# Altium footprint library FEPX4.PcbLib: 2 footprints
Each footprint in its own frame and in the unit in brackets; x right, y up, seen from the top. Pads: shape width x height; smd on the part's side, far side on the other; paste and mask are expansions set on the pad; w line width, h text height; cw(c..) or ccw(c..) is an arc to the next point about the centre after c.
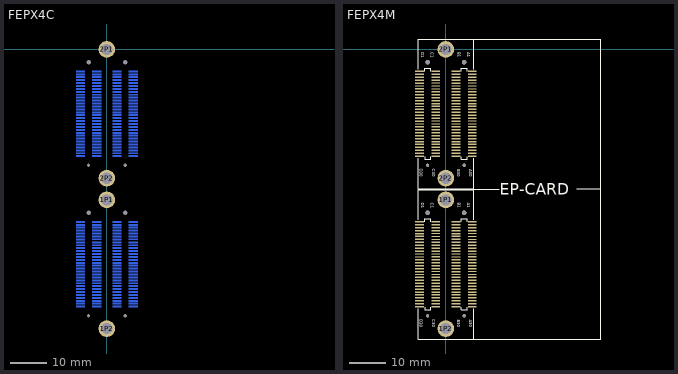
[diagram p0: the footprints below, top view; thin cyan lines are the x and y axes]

## FEPX4C [mm]
pads (252):
  round 0 hole 0.889: 0(-5,-72.869) 0(-5,-31.7) 0(5,-72.869) 0(5,-31.7)
  round 0 hole 1.2: 0(-5,-44.669) 0(-5,-3.5) 0(5,-44.669) 0(5,-3.5)
  rect 2.4x0.4 smd far side: 1A1(7.2,-47.169) 1A2(7.2,-47.969) 1A3(7.2,-48.769) 1A4(7.2,-49.569) 1A8(7.2,-52.769) 1A9(7.2,-53.569) 1A10(7.2,-54.369) 1A11(7.2,-55.169) 1A12(7.2,-55.969) 1A13(7.2,-56.769) 1A14(7.2,-57.569) 1A15(7.2,-58.369) 1A16(7.2,-59.169) 1A17(7.2,-59.969) 1A20(7.2,-62.369) 1A21(7.2,-63.169) 1A22(7.2,-63.969) 1A23(7.2,-64.769) 1A24(7.2,-65.569) 1A25(7.2,-66.369) 1A26(7.2,-67.169) 1A27(7.2,-67.969) 1A28(7.2,-68.769) 1A29(7.2,-69.569) 1A30(7.2,-70.369) 1B1(2.8,-47.169) 1B2(2.8,-47.969) 1B3(2.8,-48.769) 1B4(2.8,-49.569) 1B5(2.8,-50.369) 1B6(2.8,-51.169) 1B7(2.8,-51.969) 1B8(2.8,-52.769) 1B9(2.8,-53.569) 1B10(2.8,-54.369) 1B11(2.8,-55.169) 1B12(2.8,-55.969) 1B14(2.8,-57.569) 1B15(2.8,-58.369) 1B16(2.8,-59.169) 1B17(2.8,-59.969) 1B18(2.8,-60.769) 1B19(2.8,-61.569) 1B20(2.8,-62.369) 1B21(2.8,-63.169) 1B22(2.8,-63.969) 1B23(2.8,-64.769) 1B24(2.8,-65.569) 1B25(2.8,-66.369) 1B26(2.8,-67.169) 1B27(2.8,-67.969) 1B28(2.8,-68.769) 1B29(2.8,-69.569) 1B30(2.8,-70.369) 1C1(-2.8,-47.169) 1C2(-2.8,-47.969) 1C3(-2.8,-48.769) 1C4(-2.8,-49.569) 1C8(-2.8,-52.769) 1C9(-2.8,-53.569) 1C10(-2.8,-54.369) 1C11(-2.8,-55.169) 1C12(-2.8,-55.969) 1C13(-2.8,-56.769) 1C14(-2.8,-57.569) 1C15(-2.8,-58.369) 1C16(-2.8,-59.169) 1C17(-2.8,-59.969) 1C20(-2.8,-62.369) 1C21(-2.8,-63.169) 1C22(-2.8,-63.969) 1C23(-2.8,-64.769) 1C24(-2.8,-65.569) 1C25(-2.8,-66.369) 1C26(-2.8,-67.169) 1C27(-2.8,-67.969) 1C28(-2.8,-68.769) 1C29(-2.8,-69.569) 1C30(-2.8,-70.369) 1D1(-7.2,-47.169) 1D2(-7.2,-47.969) 1D3(-7.2,-48.769) 1D4(-7.2,-49.569) 1D5(-7.2,-50.369) 1D6(-7.2,-51.169) 1D7(-7.2,-51.969) 1D8(-7.2,-52.769) 1D9(-7.2,-53.569) 1D10(-7.2,-54.369) 1D11(-7.2,-55.169) 1D12(-7.2,-55.969) 1D14(-7.2,-57.569) 1D15(-7.2,-58.369) 1D16(-7.2,-59.169) 1D17(-7.2,-59.969) 1D18(-7.2,-60.769) 1D19(-7.2,-61.569) 1D20(-7.2,-62.369) 1D21(-7.2,-63.169) 1D22(-7.2,-63.969) 1D23(-7.2,-64.769) 1D24(-7.2,-65.569) 1D25(-7.2,-66.369) 1D26(-7.2,-67.169) 1D27(-7.2,-67.969) 1D28(-7.2,-68.769) 1D29(-7.2,-69.569) 1D30(-7.2,-70.369) 2A1(7.2,-6) 2A2(7.2,-6.8) 2A3(7.2,-7.6) 2A4(7.2,-8.4) 2A8(7.2,-11.6) 2A9(7.2,-12.4) 2A10(7.2,-13.2) 2A11(7.2,-14) 2A12(7.2,-14.8) 2A13(7.2,-15.6) 2A14(7.2,-16.4) 2A15(7.2,-17.2) 2A16(7.2,-18) 2A17(7.2,-18.8) 2A20(7.2,-21.2) 2A21(7.2,-22) 2A22(7.2,-22.8) 2A23(7.2,-23.6) 2A24(7.2,-24.4) 2A25(7.2,-25.2) 2A26(7.2,-26) 2A27(7.2,-26.8) 2A28(7.2,-27.6) 2A29(7.2,-28.4) 2A30(7.2,-29.2) 2B1(2.8,-6) 2B2(2.8,-6.8) 2B3(2.8,-7.6) 2B4(2.8,-8.4) 2B5(2.8,-9.2) 2B6(2.8,-10) 2B7(2.8,-10.8) 2B8(2.8,-11.6) 2B9(2.8,-12.4) 2B10(2.8,-13.2) 2B11(2.8,-14) 2B12(2.8,-14.8) 2B14(2.8,-16.4) 2B15(2.8,-17.2) 2B16(2.8,-18) 2B17(2.8,-18.8) 2B18(2.8,-19.6) 2B19(2.8,-20.4) 2B20(2.8,-21.2) 2B21(2.8,-22) 2B22(2.8,-22.8) 2B23(2.8,-23.6) 2B24(2.8,-24.4) 2B25(2.8,-25.2) 2B26(2.8,-26) 2B27(2.8,-26.8) 2B28(2.8,-27.6) 2B29(2.8,-28.4) 2B30(2.8,-29.2) 2C1(-2.8,-6) 2C2(-2.8,-6.8) 2C3(-2.8,-7.6) 2C4(-2.8,-8.4) 2C8(-2.8,-11.6) 2C9(-2.8,-12.4) 2C10(-2.8,-13.2) 2C11(-2.8,-14) 2C12(-2.8,-14.8) 2C13(-2.8,-15.6) 2C14(-2.8,-16.4) 2C15(-2.8,-17.2) 2C16(-2.8,-18) 2C17(-2.8,-18.8) 2C20(-2.8,-21.2) 2C21(-2.8,-22) 2C22(-2.8,-22.8) 2C23(-2.8,-23.6) 2C24(-2.8,-24.4) 2C25(-2.8,-25.2) 2C26(-2.8,-26) 2C27(-2.8,-26.8) 2C28(-2.8,-27.6) 2C29(-2.8,-28.4) 2C30(-2.8,-29.2) 2D1(-7.2,-6) 2D2(-7.2,-6.8) 2D3(-7.2,-7.6) 2D4(-7.2,-8.4) 2D5(-7.2,-9.2) 2D6(-7.2,-10) 2D7(-7.2,-10.8) 2D8(-7.2,-11.6) 2D9(-7.2,-12.4) 2D10(-7.2,-13.2) 2D11(-7.2,-14) 2D12(-7.2,-14.8) 2D14(-7.2,-16.4) 2D15(-7.2,-17.2) 2D16(-7.2,-18) 2D17(-7.2,-18.8) 2D18(-7.2,-19.6) 2D19(-7.2,-20.4) 2D20(-7.2,-21.2) 2D21(-7.2,-22) 2D22(-7.2,-22.8) 2D23(-7.2,-23.6) 2D24(-7.2,-24.4) 2D25(-7.2,-25.2) 2D26(-7.2,-26) 2D27(-7.2,-26.8) 2D28(-7.2,-27.6) 2D29(-7.2,-28.4) 2D30(-7.2,-29.2)
  rect 2.4x0.33 smd far side: 1A5(7.2,-50.369) 1A6(7.2,-51.169) 1A7(7.2,-51.969) 1A18(7.2,-60.769) 1A19(7.2,-61.569) 1B13(2.8,-56.769) 1C5(-2.8,-50.369) 1C6(-2.8,-51.169) 1C7(-2.8,-51.969) 1C18(-2.8,-60.769) 1C19(-2.8,-61.569) 1D13(-7.2,-56.769) 2A5(7.2,-9.2) 2A6(7.2,-10) 2A7(7.2,-10.8) 2A18(7.2,-19.6) 2A19(7.2,-20.4) 2B13(2.8,-15.6) 2C5(-2.8,-9.2) 2C6(-2.8,-10) 2C7(-2.8,-10.8) 2C18(-2.8,-19.6) 2C19(-2.8,-20.4) 2D13(-7.2,-15.6)
  round 4.57 hole 3.1: 1P1(0,-41.169) 1P2(0,-76.369) 2P1(0,0) 2P2(0,-35.2)
Bottom Overlay:
  lines w0.152: -7.62,-79.219 42.383,-79.219 ; -7.611,2.855 42.392,2.855 42.392,-79.193 ; -7.595,-38.192 7.62,-38.192 ; -5.8,-70.469 -5.8,-71.269 -4.2,-71.269 ; -5.8,-47.169 -5.8,-46.369 -4.2,-46.369 -4.2,-47.169 ; -5.8,-29.3 -5.8,-30.1 -4.2,-30.1 -4.2,-29.3 ; -5.8,-6 -5.8,-5.2 -4.2,-5.2 -4.2,-6 ; 4.2,-70.469 4.2,-71.269 5.8,-71.269 5.8,-70.469 ; 4.2,-47.169 4.2,-46.369 5.8,-46.369 5.8,-47.169 ; 4.2,-29.3 4.2,-30.1 5.8,-30.1 5.8,-29.3 ; 4.2,-6 4.2,-5.2 5.8,-5.2 5.8,-6 ; -4.2,-71.269 -4.2,-70.469 -4.2,-71.269
  lines w0.203: -7.62,-70.964 -7.62,-79.219 7.62,-79.219 7.62,-70.964 ; -7.62,-46.574 -7.62,-38.1 ; -7.62,-38.227 -7.62,-29.795 ; -7.62,-5.405 -7.62,2.85 7.62,2.85 7.62,-5.405 ; 7.62,-46.574 7.62,-38.227 7.62,-29.795
  text "D1" at -6.731,-0.762 h0.76
  text "C1" at -4.191,-0.762 h0.76
  text "B1" at 3.302,-0.762 h0.76
  text "A1" at 5.842,-0.762 h0.76
  text "D30" at -7.112,-32.639 h0.76
  text "C30" at -3.683,-32.639 h0.76
  text "B30" at 3.175,-32.766 h0.76
  text "A30" at 6.35,-32.766 h0.76
  text "D1" at -6.731,-41.931 h0.76
  text "C1" at -4.191,-41.931 h0.76
  text "B1" at 3.302,-41.931 h0.76
  text "A1" at 5.842,-41.931 h0.76
  text "D30" at -7.112,-73.808 h0.76
  text "C30" at -3.683,-73.808 h0.76
  text "B30" at 3.175,-73.935 h0.76
  text "A30" at 6.35,-73.935 h0.76

## FEPX4M [mm]
pads (252):
  round 0.889 hole 0.889: 0(-5,-72.869) 0(-5,-31.7) 0(5,-72.869) 0(5,-31.7)
  round 1.2 hole 1.2: 0(-5,-44.669) 0(-5,-3.5) 0(5,-44.669) 0(5,-3.5)
  rect 2.4x0.4 smd: 1A1(7.2,-47.169) 1A2(7.2,-47.969) 1A3(7.2,-48.769) 1A4(7.2,-49.569) 1A8(7.2,-52.769) 1A9(7.2,-53.569) 1A10(7.2,-54.369) 1A11(7.2,-55.169) 1A12(7.2,-55.969) 1A13(7.2,-56.769) 1A14(7.2,-57.569) 1A15(7.2,-58.369) 1A16(7.2,-59.169) 1A17(7.2,-59.969) 1A20(7.2,-62.369) 1A21(7.2,-63.169) 1A22(7.2,-63.969) 1A23(7.2,-64.769) 1A24(7.2,-65.569) 1A25(7.2,-66.369) 1A26(7.2,-67.169) 1A27(7.2,-67.969) 1A28(7.2,-68.769) 1A29(7.2,-69.569) 1A30(7.2,-70.369) 1B1(2.8,-47.169) 1B2(2.8,-47.969) 1B3(2.8,-48.769) 1B4(2.8,-49.569) 1B5(2.8,-50.369) 1B6(2.8,-51.169) 1B7(2.8,-51.969) 1B8(2.8,-52.769) 1B9(2.8,-53.569) 1B10(2.8,-54.369) 1B11(2.8,-55.169) 1B12(2.8,-55.969) 1B14(2.8,-57.569) 1B15(2.8,-58.369) 1B16(2.8,-59.169) 1B17(2.8,-59.969) 1B18(2.8,-60.769) 1B19(2.8,-61.569) 1B20(2.8,-62.369) 1B21(2.8,-63.169) 1B22(2.8,-63.969) 1B23(2.8,-64.769) 1B24(2.8,-65.569) 1B25(2.8,-66.369) 1B26(2.8,-67.169) 1B27(2.8,-67.969) 1B28(2.8,-68.769) 1B29(2.8,-69.569) 1B30(2.8,-70.369) 1C1(-2.8,-47.169) 1C2(-2.8,-47.969) 1C3(-2.8,-48.769) 1C4(-2.8,-49.569) 1C8(-2.8,-52.769) 1C9(-2.8,-53.569) 1C10(-2.8,-54.369) 1C11(-2.8,-55.169) 1C12(-2.8,-55.969) 1C13(-2.8,-56.769) 1C14(-2.8,-57.569) 1C15(-2.8,-58.369) 1C16(-2.8,-59.169) 1C17(-2.8,-59.969) 1C20(-2.8,-62.369) 1C21(-2.8,-63.169) 1C22(-2.8,-63.969) 1C23(-2.8,-64.769) 1C24(-2.8,-65.569) 1C25(-2.8,-66.369) 1C26(-2.8,-67.169) 1C27(-2.8,-67.969) 1C28(-2.8,-68.769) 1C29(-2.8,-69.569) 1C30(-2.8,-70.369) 1D1(-7.2,-47.169) 1D2(-7.2,-47.969) 1D3(-7.2,-48.769) 1D4(-7.2,-49.569) 1D5(-7.2,-50.369) 1D6(-7.2,-51.169) 1D7(-7.2,-51.969) 1D8(-7.2,-52.769) 1D9(-7.2,-53.569) 1D10(-7.2,-54.369) 1D11(-7.2,-55.169) 1D12(-7.2,-55.969) 1D14(-7.2,-57.569) 1D15(-7.2,-58.369) 1D16(-7.2,-59.169) 1D17(-7.2,-59.969) 1D18(-7.2,-60.769) 1D19(-7.2,-61.569) 1D20(-7.2,-62.369) 1D21(-7.2,-63.169) 1D22(-7.2,-63.969) 1D23(-7.2,-64.769) 1D24(-7.2,-65.569) 1D25(-7.2,-66.369) 1D26(-7.2,-67.169) 1D27(-7.2,-67.969) 1D28(-7.2,-68.769) 1D29(-7.2,-69.569) 1D30(-7.2,-70.369) 2A1(7.2,-6) 2A2(7.2,-6.8) 2A3(7.2,-7.6) 2A4(7.2,-8.4) 2A8(7.2,-11.6) 2A9(7.2,-12.4) 2A10(7.2,-13.2) 2A11(7.2,-14) 2A12(7.2,-14.8) 2A13(7.2,-15.6) 2A14(7.2,-16.4) 2A15(7.2,-17.2) 2A16(7.2,-18) 2A17(7.2,-18.8) 2A20(7.2,-21.2) 2A21(7.2,-22) 2A22(7.2,-22.8) 2A23(7.2,-23.6) 2A24(7.2,-24.4) 2A25(7.2,-25.2) 2A26(7.2,-26) 2A27(7.2,-26.8) 2A28(7.2,-27.6) 2A29(7.2,-28.4) 2A30(7.2,-29.2) 2B1(2.8,-6) 2B2(2.8,-6.8) 2B3(2.8,-7.6) 2B4(2.8,-8.4) 2B5(2.8,-9.2) 2B6(2.8,-10) 2B7(2.8,-10.8) 2B8(2.8,-11.6) 2B9(2.8,-12.4) 2B10(2.8,-13.2) 2B11(2.8,-14) 2B12(2.8,-14.8) 2B14(2.8,-16.4) 2B15(2.8,-17.2) 2B16(2.8,-18) 2B17(2.8,-18.8) 2B18(2.8,-19.6) 2B19(2.8,-20.4) 2B20(2.8,-21.2) 2B21(2.8,-22) 2B22(2.8,-22.8) 2B23(2.8,-23.6) 2B24(2.8,-24.4) 2B25(2.8,-25.2) 2B26(2.8,-26) 2B27(2.8,-26.8) 2B28(2.8,-27.6) 2B29(2.8,-28.4) 2B30(2.8,-29.2) 2C1(-2.8,-6) 2C2(-2.8,-6.8) 2C3(-2.8,-7.6) 2C4(-2.8,-8.4) 2C8(-2.8,-11.6) 2C9(-2.8,-12.4) 2C10(-2.8,-13.2) 2C11(-2.8,-14) 2C12(-2.8,-14.8) 2C13(-2.8,-15.6) 2C14(-2.8,-16.4) 2C15(-2.8,-17.2) 2C16(-2.8,-18) 2C17(-2.8,-18.8) 2C20(-2.8,-21.2) 2C21(-2.8,-22) 2C22(-2.8,-22.8) 2C23(-2.8,-23.6) 2C24(-2.8,-24.4) 2C25(-2.8,-25.2) 2C26(-2.8,-26) 2C27(-2.8,-26.8) 2C28(-2.8,-27.6) 2C29(-2.8,-28.4) 2C30(-2.8,-29.2) 2D1(-7.2,-6) 2D2(-7.2,-6.8) 2D3(-7.2,-7.6) 2D4(-7.2,-8.4) 2D5(-7.2,-9.2) 2D6(-7.2,-10) 2D7(-7.2,-10.8) 2D8(-7.2,-11.6) 2D9(-7.2,-12.4) 2D10(-7.2,-13.2) 2D11(-7.2,-14) 2D12(-7.2,-14.8) 2D14(-7.2,-16.4) 2D15(-7.2,-17.2) 2D16(-7.2,-18) 2D17(-7.2,-18.8) 2D18(-7.2,-19.6) 2D19(-7.2,-20.4) 2D20(-7.2,-21.2) 2D21(-7.2,-22) 2D22(-7.2,-22.8) 2D23(-7.2,-23.6) 2D24(-7.2,-24.4) 2D25(-7.2,-25.2) 2D26(-7.2,-26) 2D27(-7.2,-26.8) 2D28(-7.2,-27.6) 2D29(-7.2,-28.4) 2D30(-7.2,-29.2)
  rect 2.4x0.33 smd: 1A5(7.2,-50.369) 1A6(7.2,-51.169) 1A7(7.2,-51.969) 1A18(7.2,-60.769) 1A19(7.2,-61.569) 1B13(2.8,-56.769) 1C5(-2.8,-50.369) 1C6(-2.8,-51.169) 1C7(-2.8,-51.969) 1C18(-2.8,-60.769) 1C19(-2.8,-61.569) 1D13(-7.2,-56.769) 2A5(7.2,-9.2) 2A6(7.2,-10) 2A7(7.2,-10.8) 2A18(7.2,-19.6) 2A19(7.2,-20.4) 2B13(2.8,-15.6) 2C5(-2.8,-9.2) 2C6(-2.8,-10) 2C7(-2.8,-10.8) 2C18(-2.8,-19.6) 2C19(-2.8,-20.4) 2D13(-7.2,-15.6)
  round 4.57 hole 3.1: 1P1(0,-41.169) 1P2(0,-76.369) 2P1(0,0) 2P2(0,-35.2)
Top Overlay:
  lines w0.127: -7.62,-79.219 42.383,-79.219 ; -7.611,2.855 42.392,2.855 42.392,-79.193 ; -7.595,-38.192 14.668,-38.192 ; 35.865,-38.159 42.319,-38.167
  lines w0.152: -5.8,-70.469 -5.8,-71.269 -4.2,-71.269 ; -5.8,-47.169 -5.8,-46.369 -4.2,-46.369 -4.2,-47.169 ; -5.8,-29.3 -5.8,-30.1 -4.2,-30.1 ; -5.8,-6 -5.8,-5.2 -4.2,-5.2 -4.2,-6 ; 4.2,-47.169 4.2,-46.369 5.8,-46.369 5.8,-47.169 ; 4.2,-6 4.2,-5.2 5.8,-5.2 5.8,-6 ; 5.8,-70.469 5.8,-71.269 4.2,-71.269 ; 5.8,-29.3 5.8,-30.1 4.2,-30.1 ; -4.2,-71.269 -4.2,-70.469 -4.2,-71.269 ; -4.2,-30.1 -4.2,-29.3 -4.2,-30.1 ; 4.2,-71.269 4.2,-70.469 4.2,-71.269 ; 4.2,-30.1 4.2,-29.3 4.2,-30.1
  lines w0.203: -7.62,-70.964 -7.62,-79.219 7.62,-79.219 7.62,-70.964 ; -7.62,-46.574 -7.62,-38.319 7.62,-38.319 7.62,-46.574 ; -7.62,-29.795 -7.62,-38.05 7.62,-38.05 7.62,-29.795 ; -7.62,-5.405 -7.62,2.85 7.62,2.85 7.62,-5.405
  text "EP-CARD" at 14.745,-39.696 h3.05
  text "C30" at -3.683,-73.808 h0.76
  text "D30" at -7.112,-73.808 h0.76
  text "C1" at -4.191,-41.931 h0.76
  text "D1" at -6.731,-41.931 h0.76
  text "A30" at 6.35,-73.935 h0.76
  text "B30" at 3.175,-73.935 h0.76
  text "A1" at 5.842,-41.931 h0.76
  text "B1" at 3.302,-41.931 h0.76
  text "C30" at -3.683,-32.639 h0.76
  text "D30" at -7.112,-32.639 h0.76
  text "C1" at -4.191,-0.762 h0.76
  text "D1" at -6.731,-0.762 h0.76
  text "A30" at 6.35,-32.766 h0.76
  text "B30" at 3.175,-32.766 h0.76
  text "A1" at 5.842,-0.762 h0.76
  text "B1" at 3.302,-0.762 h0.76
